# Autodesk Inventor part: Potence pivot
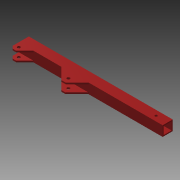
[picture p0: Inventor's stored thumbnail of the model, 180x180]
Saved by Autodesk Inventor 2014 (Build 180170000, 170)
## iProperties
Created: 2015-06
Part Number: Potence pivot
Material: Générique
Document SubType Name: Modeling
Designer: OL
Density: 1 g/cm^3
Appearance: Par défaut
Author: OL
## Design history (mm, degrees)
sketch "Esquisse1"
  geometry: L1 (-35, 35)-(35, 35); L2 (35, 35)-(35, -35); L3 (35, -35)-(-35, -35); L4 (-35, -35)-(-35, 35); L5 (27.5, -27.5)-(-27.5, -27.5); L6 (-27.5, -27.5)-(-27.5, 27.5); L7 (-27.5, 27.5)-(27.5, 27.5); L8 (27.5, 27.5)-(27.5, -27.5); 1 further point
  constraints: 16 end point, 4 parallel, 2 horizontal, 2 perpendicular
  dimensions: "d1" = 7.5 distance between parallel lines of L1 L7 (= d6); "d2" = 35 distance from line of L1 point (0, 0) (= d5); "d3" = 70 distance of L3.end L1.start; "d4" = 70 distance of L2.end L3.end; "d5" = 35 distance from line of point (0, 0) L4; "d6" = 7.5 distance between parallel lines of L2 L8; "d33" = 7.5 distance between parallel lines of L4 L6 (= d6); "d34" = 7.5 distance between parallel lines of L3 L5 (= d6)
extrude "Extrusion1" new body sketch "Esquisse1" distance "d8" = 1000; taper "d9" = 0 deg
sketch "Esquisse2"
  geometry: L1 (0, 0)-(0, 70) reference; L2 (0, 0)-(1000, 0) reference; L3 (0, 70)-(1000, 70) reference; L4 (0, 0)-(0, -43); L5 (0, -43)-(17, -60); L6 (17, -60)-(40, -60); L7 (40, -60)-(100, 0); C1 r 10 at (30, -30); 1 further point
  constraints: 8 end point, 2 perpendicular, 1 centre point, 1 point on line
  dimensions: "d10" = 100 distance from line of L1 L7.end; "d11" = 60 distance between parallel lines of L2 L6; "d12" = 17 horizontal distance of L4.end L5.end; "d13" = 17 horizontal distance of L4.end L5.end; "d14" = 23 distance of L5.end L6.end; "d15" = 20 diameter of C1; "d16" = 30 distance from line of L2 C1.centre; "d17" = 30 distance from line of L4 C1.centre
extrude "Extrusion2" join sketch "Esquisse2" distance "d18" = 10; taper "d19" = 0 deg
mirror "Symétrie1"
sketch "Esquisse3"
  geometry: L1 (0, -113)-(0, 0) reference; L2 (100, -70)-(1000, -70) reference; L3 (0, 0)-(1000, 0) reference; L4 (295, -70)-(375, -150); L5 (375, -150)-(405, -150); L6 (405, -150)-(485, -70); C1 r 10 at (390, -115); 1 further point
  constraints: 6 end point, 2 point on line, 1 centre point, 1 parallel, 1 perpendicular
  dimensions: "d20" = 295 distance from line of L1 L4.start; "d21" = 190 distance of L6.end L4.start; "d22" = 80 distance between parallel lines of L2 L5; "d23" = 30 distance of L4.end L5.end; "d24" = 95 horizontal distance of L4.start C1.centre; "d25" = 45 distance from line of L2 C1.centre; "d26" = 20 diameter of C1
extrude "Extrusion3" join sketch "Esquisse3" distance "d27" = 10; taper "d28" = 0 deg
mirror "Symétrie2"
sketch "Esquisse4"
  geometry: L1 (1000, 0)-(1000, -70) reference; L2 (485, -70)-(1000, -70) reference; C1 r 8.5 at (920, -35); 1 further point
  constraints: 1 centre point
  dimensions: "d29" = 80 distance from line of L1 C1.centre; "d30" = 17 diameter of C1; "d35" = 35 distance from line of L2 C1.centre
extrude "Extrusion4" cut sketch "Esquisse4" distance "d31" = 80; taper "d32" = 0 deg
node "Solide1"
